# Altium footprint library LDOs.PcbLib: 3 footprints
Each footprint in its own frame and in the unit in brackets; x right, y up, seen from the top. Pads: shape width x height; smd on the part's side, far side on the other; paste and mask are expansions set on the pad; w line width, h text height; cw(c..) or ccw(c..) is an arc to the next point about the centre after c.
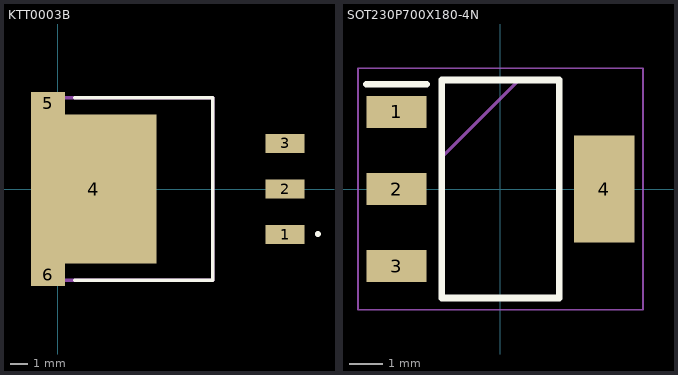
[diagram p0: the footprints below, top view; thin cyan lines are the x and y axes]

## KTT0003B [mm]
pads (6):
  rect 2.16x1.07 smd: 1(12.67,-2.54) 2(12.67,0) 3(12.67,2.54)
  rect 7x8.33 smd: 4(2,0)
  rect 1.91x1.235 smd: 5(-0.545,4.782) 6(-0.545,-4.782)
Top Overlay:
  circle w0.2: c14.497,-2.51 r0.065
  lines w0.2: 0.94,-5.08 8.64,-5.08 8.64,5.08 0.94,5.08
Mechanical 13:
  lines w0.2: 0,-5.08 0,5.08 8.64,5.08 8.64,-5.08 0,-5.08
3D body "LM1085ISX-ADJ_NOPB.stp": height 4.54, standoff 0, extent -1.517,-5.08 13.722,5.08

## PCBComponent_1 [mm]

## SOT230P700X180-4N [mm]
pads (4):
  rect 1.8x0.95 smd: 1(-3.1,2.3) 2(-3.1,0) 3(-3.1,-2.3)
  rect 1.8x3.2 smd: 4(3.1,0)
Top Overlay:
  lines w0.2: -4,3.125 -2.2,3.125 ; -1.75,-3.25 -1.75,3.25 1.75,3.25 1.75,-3.25 -1.75,-3.25
Mechanical 13:
  lines w0.1: -1.75,0.95 0.55,3.25 ; -1.75,-3.25 -1.75,3.25 1.75,3.25 1.75,-3.25 -1.75,-3.25
Mechanical 15:
  lines w0.05: -4.25,-3.6 -4.25,3.6 4.25,3.6 4.25,-3.6 -4.25,-3.6
3D body "TL1963A-33DCYR.stp": height 1.68, standoff 0, extent -3.5,-3.25 3.5,3.25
